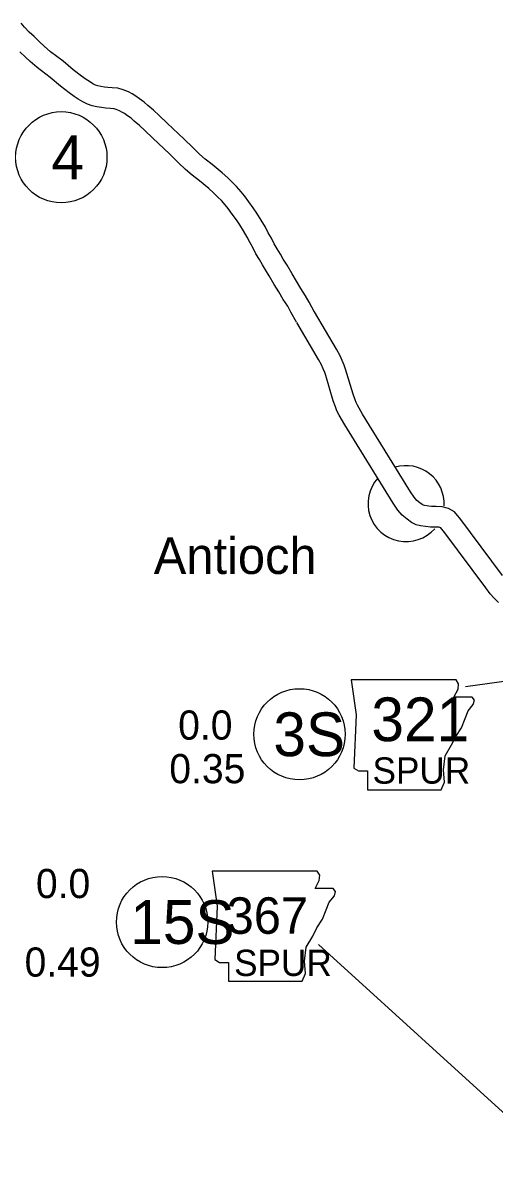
# Model space of a CAD drawing. Extents: x -939622 to -934222, y 1383701 to 1385301.
# Drawn here: x -936430.9 to -936410.4, y 1384450.8 to 1384500.9 of the extents above; entities that cross this region are included whole.
import ezdxf

# ---------------------------------------------------------------- set-up
doc = ezdxf.new("R2010")
doc.units = 0
for name, color, linetype in [('10', 7, 'Continuous'), ('21', 7, 'Continuous'), ('24', 7, 'Continuous'), ('25', 7, 'Continuous'), ('27', 7, 'Continuous')]:
    doc.layers.add(name, color=color, linetype=linetype)

msp = doc.modelspace()

# ---------------------------------------------------------------- linework, layer by layer
at = {"layer": '10'}
for points in [[(-936418.236, 1384488.4), (-936418.478, 1384488.825), (-936418.629, 1384489.109), (-936418.83, 1384489.419), (-936419.018, 1384489.739), (-936419.212, 1384490.059), (-936419.433, 1384490.44), (-936419.596, 1384490.695), (-936419.72, 1384490.906), (-936419.86, 1384491.146), (-936419.994, 1384491.367), (-936420.113, 1384491.601), (-936420.245, 1384491.834), (-936420.372, 1384492.086), (-936420.55, 1384492.393), (-936420.737, 1384492.686), (-936420.898, 1384492.92), (-936421.089, 1384493.18), (-936421.281, 1384493.44), (-936421.425, 1384493.618), (-936421.619, 1384493.851), (-936421.803, 1384494.029), (-936422.005, 1384494.231), (-936422.248, 1384494.444), (-936422.675, 1384494.798), (-936422.979, 1384495.033), (-936423.224, 1384495.248), (-936423.525, 1384495.538), (-936423.902, 1384495.909), (-936424.633, 1384496.598), (-936424.981, 1384496.93), (-936425.232, 1384497.163), (-936425.465, 1384497.365), (-936425.625, 1384497.508), (-936425.826, 1384497.656), (-936425.996, 1384497.773), (-936426.152, 1384497.867), (-936426.314, 1384497.952), (-936426.543, 1384498.046), (-936426.77, 1384498.113), (-936427.024, 1384498.133), (-936427.21, 1384498.146), (-936427.357, 1384498.163), (-936427.504, 1384498.188), (-936427.644, 1384498.22), (-936427.742, 1384498.254), (-936427.856, 1384498.311), (-936428.007, 1384498.4), (-936428.148, 1384498.495), (-936428.347, 1384498.64), (-936428.703, 1384498.907), (-936429.147, 1384499.283), (-936429.699, 1384499.7), (-936429.962, 1384499.943), (-936430.164, 1384500.129), (-936430.407, 1384500.356), (-936430.615, 1384500.554), (-936430.814, 1384500.772), (-936430.963, 1384500.942)], [(-936419.019, 1384487.955), (-936419.267, 1384488.391), (-936419.405, 1384488.652), (-936419.596, 1384488.946), (-936419.791, 1384489.278), (-936419.985, 1384489.599), (-936420.202, 1384489.971), (-936420.364, 1384490.225), (-936420.497, 1384490.452), (-936420.633, 1384490.686), (-936420.78, 1384490.928), (-936420.907, 1384491.175), (-936421.039, 1384491.41), (-936421.164, 1384491.657), (-936421.319, 1384491.925), (-936421.487, 1384492.189), (-936421.631, 1384492.399), (-936421.813, 1384492.646), (-936421.993, 1384492.888), (-936422.121, 1384493.047), (-936422.28, 1384493.238), (-936422.434, 1384493.388), (-936422.62, 1384493.574), (-936422.831, 1384493.759), (-936423.237, 1384494.095), (-936423.551, 1384494.338), (-936423.833, 1384494.585), (-936424.153, 1384494.893), (-936424.527, 1384495.261), (-936425.252, 1384495.944), (-936425.598, 1384496.275), (-936425.833, 1384496.493), (-936426.059, 1384496.689), (-936426.194, 1384496.809), (-936426.348, 1384496.923), (-936426.483, 1384497.016), (-936426.595, 1384497.083), (-936426.695, 1384497.136), (-936426.841, 1384497.196), (-936426.935, 1384497.223), (-936427.09, 1384497.235), (-936427.294, 1384497.249), (-936427.485, 1384497.272), (-936427.681, 1384497.305), (-936427.892, 1384497.354), (-936428.09, 1384497.422), (-936428.286, 1384497.52), (-936428.488, 1384497.639), (-936428.665, 1384497.758), (-936428.881, 1384497.916), (-936429.264, 1384498.203), (-936429.71, 1384498.58), (-936430.277, 1384499.008), (-936430.573, 1384499.282), (-936430.776, 1384499.47), (-936431.024, 1384499.701)], [(-936410.093, 1384476.96), (-936411.939, 1384479.451), (-936412.04, 1384479.564), (-936412.173, 1384479.735), (-936412.427, 1384479.876), (-936412.699, 1384479.949), (-936412.968, 1384479.966), (-936413.168, 1384479.961), (-936413.289, 1384479.976), (-936413.465, 1384480.009), (-936413.534, 1384480.024), (-936413.573, 1384480.043), (-936413.668, 1384480.112), (-936413.799, 1384480.226), (-936413.915, 1384480.358), (-936414.075, 1384480.594), (-936416.157, 1384483.962), (-936416.382, 1384484.353), (-936416.439, 1384484.468), (-936416.483, 1384484.592), (-936416.572, 1384484.829), (-936416.895, 1384485.915), (-936416.956, 1384486.093), (-936417.038, 1384486.298), (-936417.134, 1384486.506), (-936417.283, 1384486.783), (-936418.24, 1384488.406)], [(-936410.264, 1384475.797), (-936410.454, 1384475.983), (-936410.625, 1384476.163), (-936410.818, 1384476.427), (-936412.635, 1384478.88), (-936412.731, 1384478.985), (-936412.77, 1384479.036), (-936412.846, 1384479.056), (-936412.986, 1384479.065), (-936413.211, 1384479.06), (-936413.427, 1384479.086), (-936413.643, 1384479.127), (-936413.828, 1384479.166), (-936414.038, 1384479.268), (-936414.229, 1384479.408), (-936414.436, 1384479.587), (-936414.629, 1384479.807), (-936414.83, 1384480.104), (-936416.93, 1384483.501), (-936417.175, 1384483.928), (-936417.269, 1384484.116), (-936417.329, 1384484.284), (-936417.426, 1384484.542), (-936417.751, 1384485.64), (-936417.8, 1384485.778), (-936417.865, 1384485.942), (-936417.94, 1384486.103), (-936418.068, 1384486.342), (-936419.015, 1384487.949)]]:
    msp.add_lwpolyline(points, dxfattribs=at)
at = {"layer": '21'}
for p, q in [((-936411.692, 1384472.151), (-936400.819, 1384473.611)), ((-936406.936, 1384450.816), (-936418.073, 1384460.942))]:
    msp.add_line(p, q, dxfattribs=at)
for points in [[(-936416.659, 1384472.438), (-936416.431, 1384470.915), (-936416.532, 1384468.606), (-936416.329, 1384468.479), (-936415.949, 1384468.479), (-936415.949, 1384467.667), (-936412.751, 1384467.667), (-936412.599, 1384467.997), (-936412.65, 1384468.53), (-936412.574, 1384469.139), (-936412.294, 1384469.621), (-936412.117, 1384469.976), (-936411.863, 1384470.357), (-936411.711, 1384470.763), (-936411.584, 1384471.093), (-936411.355, 1384471.372), (-936411.305, 1384471.55), (-936411.406, 1384471.677), (-936412.193, 1384471.677), (-936412.015, 1384472.032), (-936411.99, 1384472.26), (-936412.095, 1384472.436)], [(-936422.686, 1384464.132), (-936422.458, 1384462.61), (-936422.559, 1384460.3), (-936422.356, 1384460.173), (-936421.975, 1384460.173), (-936421.975, 1384459.361), (-936418.778, 1384459.361), (-936418.626, 1384459.691), (-936418.676, 1384460.224), (-936418.6, 1384460.833), (-936418.321, 1384461.315), (-936418.143, 1384461.671), (-936417.89, 1384462.051), (-936417.737, 1384462.457), (-936417.611, 1384462.787), (-936417.382, 1384463.066), (-936417.331, 1384463.244), (-936417.433, 1384463.371), (-936418.22, 1384463.371), (-936418.042, 1384463.726), (-936418.017, 1384463.955), (-936418.122, 1384464.13)]]:
    msp.add_lwpolyline(points, close=True, dxfattribs=at)
at = {"layer": '24'}
for start, end in [(356.8477, 106.7465), (137.981, 318.8291)]:
    msp.add_arc((-936414.272, 1384480.083), 1.65, start, end, dxfattribs=at)
at = {"layer": '27'}
for centre in [(-936429.225, 1384495.118), (-936418.893, 1384470.072), (-936424.852, 1384461.922)]:
    msp.add_circle(centre, 1.98, dxfattribs=at)

# ---------------------------------------------------------------- texts
at = {"layer": '21'}
for s, height, p in [('321', 1.9008, (-936415.777, 1384469.771)), ('SPUR', 1.1405, (-936415.727, 1384467.929)), ('367', 1.584, (-936422.054, 1384461.411)), ('SPUR', 1.1405, (-936421.73, 1384459.581))]:
    msp.add_text(s, height=height, dxfattribs=at).set_placement(p)
at = {"layer": '24'}
msp.add_text('Antioch', height=1.584, dxfattribs=at).set_placement((-936425.215, 1384477.031))
at = {"layer": '25'}
for s, p in [('0.0', (-936424.155, 1384469.84)), ('0.35', (-936424.539, 1384467.947)), ('0.0', (-936430.325, 1384462.961)), ('0.49', (-936430.816, 1384459.552))]:
    msp.add_text(s, height=1.2672, dxfattribs=at).set_placement(p)
at = {"layer": '27'}
for s, height, p in [('4', 1.901, (-936429.65, 1384494.167)), ('3S', 1.9008, (-936420.027, 1384469.122)), ('15S', 1.9008, (-936426.234, 1384460.971))]:
    msp.add_text(s, height=height, dxfattribs=at).set_placement(p)

doc.saveas('drawing.dxf')
